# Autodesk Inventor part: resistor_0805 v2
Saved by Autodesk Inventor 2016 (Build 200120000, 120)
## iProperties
Created: 2016-09
Part Number: resistor_0805 v2
Material: Generic
Document SubType Name: Modeling
Designer: Administrator
Appearance: Generic
Author: Administrator
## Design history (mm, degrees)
feature "Body6"
feature "Body8"
feature "Body19"
body "Solid1"
body "Solid2"
body "Solid3"
